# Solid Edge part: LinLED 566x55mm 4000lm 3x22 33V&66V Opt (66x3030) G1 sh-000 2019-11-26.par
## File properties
Author: sylwester.cabaj
Template: iso metric part.par
Last saved by: sylwester.cabaj
Revision: 1
Application: Solid Edge
Gęstość: 0,000 kg/m^3
Dokładność: 0,990
Username: sylwester.cabaj
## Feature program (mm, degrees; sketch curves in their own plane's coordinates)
body "unnamed Body 1"
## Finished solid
Body 1: solid body, 1222 faces, 3098 edges, 1954 vertices.
  Faces by surface: plane 694, cylinder 260, spline 160, cone 52, torus 22, sphere 20, spun 14
  Edges by curve: line 1956, curve on surface 564, circle 358, ellipse 132, spline 76, intersection 12
Bounding box of the edges (mm; curved faces can reach further): 566.000 x 5.050 x 55.000, from (-283, -5.05, -27.5) to (283, 0, 27.5).
Cylindrical faces by radius (mm): R0.2 x78, R0.2002 x4, R0.2169 x6, R0.25 x24, R0.3 x4, R0.3373 x6, R0.4 x16, R0.4006 x4, R0.4008 x4, R0.5 x8, R0.525 x4, R0.6 x24, R0.75 x16, R1 x14, R1.0894 x4, R1.1 x28, R2.375 x16
Conical faces (half-angle, radius in mm at the cone's reference point): 0.5 deg R0.5056 x8, 0.5 deg R1.0082 x8, 1 deg R0.5511 x4, 10 deg R0.2132 x4, 10 deg R0.4132 x4, 18.4844 deg R1.0657 x8, 27.363 deg R0.6214 x4, 45 deg R0.575 x4, 45 deg R0.625 x8
Toroidal faces (ring radius, tube radius in mm): R0.1 r0.2 x2, R0.8 r0.2 x8, R0.8522 r0.3 x4, R0.9002 r0.2 x2, R0.9018 r0.2 x2, R1.3 r0.2 x4
Spherical faces by radius (mm): R0.2 x16, R0.6 x4
Planar faces by outward normal: +x 94, +y 15, +z 109, -x 94, -y 105, -z 109, oblique 168
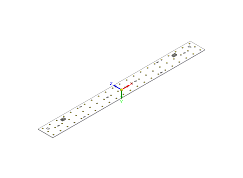
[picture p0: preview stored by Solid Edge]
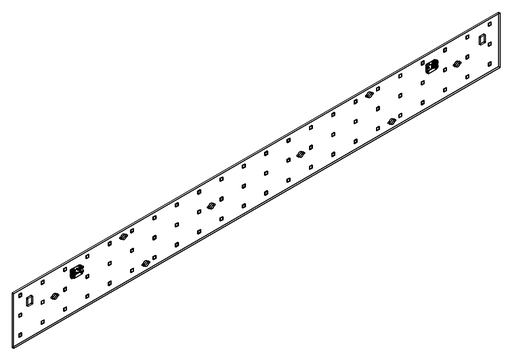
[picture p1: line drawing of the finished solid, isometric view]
